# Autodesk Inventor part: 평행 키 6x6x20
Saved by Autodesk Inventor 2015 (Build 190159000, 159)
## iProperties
Created: 2026-07
Part Number: 평행 키 6x6x20
Material: 일반
Document SubType Name: Modeling
Designer: USER
Density: 1 g/cm^3
Appearance: 기본값
Author: USER
Author: jhkim
Creation Date: 2026-07-01
Sending System: Autodesk Inventor 2027
Preprocessor: ST-DEVELOPER v20.1
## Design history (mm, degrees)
node "평행 키 6x6x201"
body "Solid1"
node "기준1"
